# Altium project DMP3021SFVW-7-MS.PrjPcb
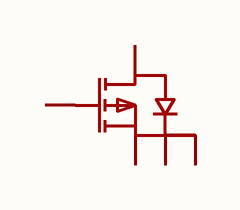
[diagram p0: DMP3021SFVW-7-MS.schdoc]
1 sheet, 1 parts. Net scope: global (net labels, ports and power ports of the same name join across sheets).

## Sheet DMP3021SFVW-7-MS.schdoc
size 127 x 101 mm

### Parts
Q?  dmp3021sfvw-7-ms  [PDFN3333-8_L3.1-W3.2-P0.65-LS3.4-BL_1]  (value not drawn)

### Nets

Not connected (* = marked no-connect by the designer): Q? 1(S) 2(S) 3(S) 4(G) 5(D)

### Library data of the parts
Q? = dmp3021sfvw-7-ms: 数量:1个P沟道;漏源电压(Vdss):30V;连续漏极电流(Id):-;导通电阻(RDS(on)):9mΩ@10V;耗散功率(Pd):37W;阈值电压(Vgs(th)):1.2V;; Manufacturer: MSKSEMI(美森科); AddInBom: yes; ModelId: c288237aeb774e1d92142cc9eea176d4; ModelTransform: 118.8974,118.8974,0,90,0,0,0,19.486,0; Number: 1个P沟道; Drain to Source Voltage: 30V; Pd - Power Dissipation: 37W; Gate Threshold Voltage (Vgs(th)): 1.2V; Gate Charge(Qg): 22nC; Input Capacitance(Ciss): 2.215nF; Reverse Transfer Capacitance (Crss@Vds): 237pF; Type: P沟道; Output Capacitance(Coss): 310pF; Vgs: ±20V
